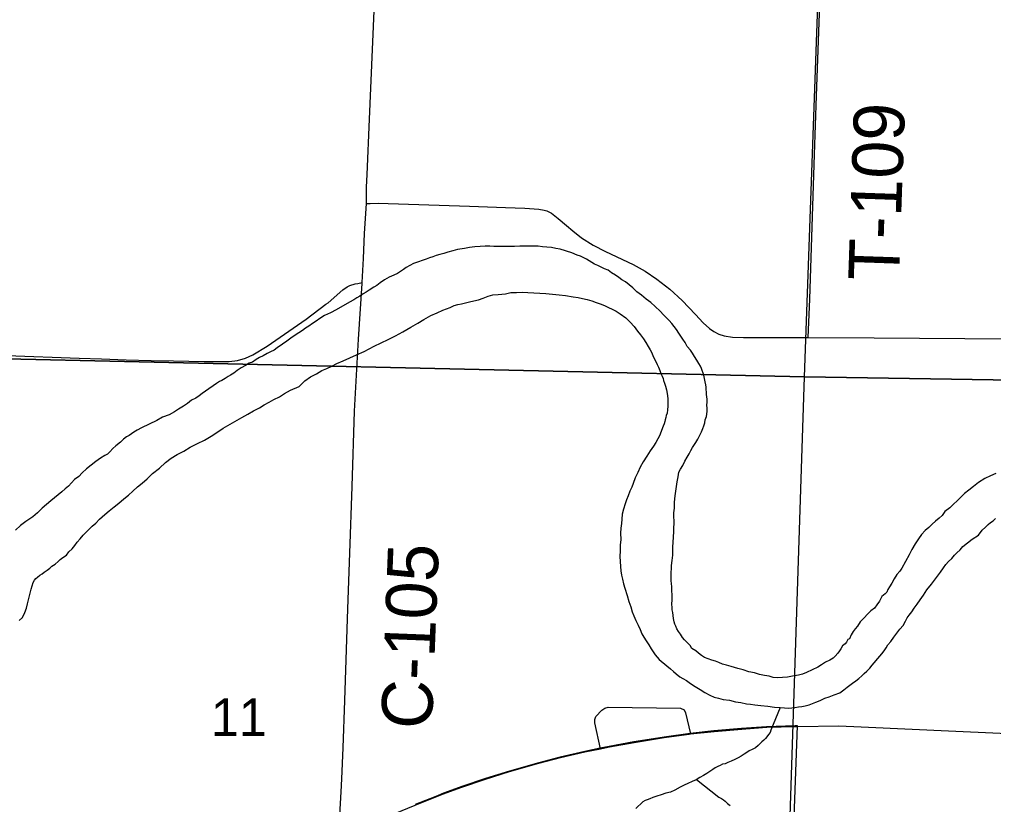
# Model space of a CAD drawing. Extents: x 2.4 to 73.1, y 4.5 to 25.6.
# Drawn here: x 29.555 to 30.099, y 20.902 to 21.341 of the extents above; entities that cross this region are included whole.
import ezdxf

# ---------------------------------------------------------------- set-up
doc = ezdxf.new("R2010")
doc.units = 0
for name, color, linetype in [('GM_X_Corporation', 7, 'Continuous'), ('GM_X_County_Road', 7, 'Continuous'), ('GM_X_County_Road_Text', 7, 'Continuous'), ('GM_X_Interchange_Ramps', 7, 'Continuous'), ('GM_X_Major_River', 7, 'Continuous'), ('GM_X_Minor_River', 7, 'Continuous'), ('GM_X_Section', 7, 'Continuous'), ('GM_X_Section_Text', 7, 'Continuous'), ('GM_X_Township_Road', 7, 'Continuous'), ('GM_X_Township_Road_Text', 7, 'Continuous'), ('GM_X_US_Shield', 7, 'Continuous')]:
    doc.layers.add(name, color=color, linetype=linetype)

msp = doc.modelspace()

# ---------------------------------------------------------------- linework, layer by layer
at = {"layer": 'GM_X_Corporation'}
msp.add_lwpolyline([(29.9783, 20.63829), (29.98962, 20.94583), (29.98829, 20.94583), (29.97224, 20.94531), (29.95828, 20.94435), (29.94277, 20.94304), (29.92959, 20.94158), (29.91498, 20.93958), (29.89808, 20.93689), (29.88431, 20.9344), (29.87929, 20.93336), (29.87059, 20.93156), (29.85696, 20.92837), (29.8449, 20.92525), (29.82845, 20.92053), (29.81508, 20.91636), (29.80182, 20.91189), (29.79158, 20.90816), (29.78727, 20.90644), (29.77572, 20.90185)], dxfattribs=at)
at = {"layer": 'GM_X_County_Road'}
for points in [[(29.74852, 21.23783), (29.74859, 21.24695), (29.74896, 21.25396), (29.75029, 21.28495), (29.75378, 21.36727), (29.75425, 21.38437), (29.75423, 21.3862)], [(29.74616, 21.19359), (29.74686, 21.207), (29.74742, 21.22097), (29.74852, 21.23783)], [(29.73275, 20.88211), (29.73361, 20.89602), (29.73437, 20.90895), (29.73479, 20.9163), (29.73556, 20.93365), (29.73646, 20.96006), (29.73816, 21.01134), (29.73923, 21.04241), (29.74049, 21.07969), (29.74186, 21.12165), (29.74411, 21.162), (29.74613, 21.19303), (29.74616, 21.19359)], [(29.92971, 20.94131), (29.94289, 20.94276), (29.95839, 20.94407), (29.97236, 20.94503), (29.98841, 20.94555), (29.98929, 20.94555)], [(29.98929, 20.94555), (29.98973, 20.94555), (30.01271, 20.94578), (30.02518, 20.94536), (30.0781, 20.9429), (30.11546, 20.94119), (30.18551, 20.93827), (30.21656, 20.93706)], [(29.87941, 20.93308), (29.88442, 20.93412), (29.8982, 20.93662), (29.9151, 20.93931), (29.92897, 20.94123), (29.92971, 20.94131)], [(29.73275, 20.88211), (29.74306, 20.88722), (29.75435, 20.89247), (29.76434, 20.89681), (29.77584, 20.90157), (29.78739, 20.90617), (29.7917, 20.90788), (29.80193, 20.91161), (29.8152, 20.91609), (29.82857, 20.92026), (29.84502, 20.92497), (29.85708, 20.92809), (29.87071, 20.93128), (29.87941, 20.93308)]]:
    msp.add_lwpolyline(points, dxfattribs=at)
at = {"layer": 'GM_X_Interchange_Ramps'}
msp.add_lwpolyline([(29.87941, 20.93308), (29.87631, 20.94754), (29.87631, 20.94934), (29.8768, 20.95107), (29.88025, 20.95469), (29.88189, 20.95576), (29.88378, 20.95622), (29.92415, 20.95576), (29.9262, 20.95477), (29.92702, 20.95304), (29.92971, 20.94131)], dxfattribs=at)
at = {"layer": 'GM_X_Major_River'}
for points in [[(29.84457, 21.21388), (29.84172, 21.21395), (29.83887, 21.21401), (29.8343, 21.21392), (29.83126, 21.2138), (29.82802, 21.21369), (29.82517, 21.21375), (29.82251, 21.21381), (29.81985, 21.21387), (29.81757, 21.21392), (29.81491, 21.21398), (29.81206, 21.21385), (29.8092, 21.21354), (29.80615, 21.21323), (29.80329, 21.21272), (29.79947, 21.21205), (29.79679, 21.21135), (29.79412, 21.21065), (29.79182, 21.20994), (29.78952, 21.20923), (29.78761, 21.2087), (29.78569, 21.20799), (29.78378, 21.20746), (29.78186, 21.20674), (29.77975, 21.20603), (29.77764, 21.20513), (29.77477, 21.20424), (29.77285, 21.20315), (29.77073, 21.20205), (29.76918, 21.20095), (29.76764, 21.19984), (29.7659, 21.19874), (29.76379, 21.19784), (29.76129, 21.19657), (29.7586, 21.19511), (29.75628, 21.19345), (29.75434, 21.19197), (29.75261, 21.19106), (29.7501, 21.18941), (29.74837, 21.18831), (29.74664, 21.1874), (29.7449, 21.18611), (29.74316, 21.18501), (29.74142, 21.18391), (29.73911, 21.18263), (29.73161, 21.17843), (29.72853, 21.17679), (29.72507, 21.17515), (29.72256, 21.1735), (29.72044, 21.17203), (29.71832, 21.17075), (29.71638, 21.16927), (29.71446, 21.16817), (29.71272, 21.16688), (29.71079, 21.1656), (29.70866, 21.16413), (29.70634, 21.16247), (29.70403, 21.16081), (29.70152, 21.15916), (29.69862, 21.15713), (29.69688, 21.15584), (29.69496, 21.15493), (29.69304, 21.15403), (29.69073, 21.15275), (29.6888, 21.15165), (29.68688, 21.15056), (29.68475, 21.14908), (29.68303, 21.14855), (29.68091, 21.14727), (29.67841, 21.146), (29.67628, 21.14453), (29.67435, 21.14305), (29.67261, 21.14195), (29.67126, 21.14103), (29.66953, 21.13993), (29.66856, 21.13938), (29.6676, 21.13883), (29.66645, 21.13829), (29.66471, 21.13719), (29.66278, 21.1359), (29.66046, 21.13424), (29.65853, 21.13296), (29.6566, 21.13167), (29.65505, 21.13038), (29.65312, 21.12909), (29.65081, 21.12781), (29.64849, 21.12596), (29.64618, 21.1245), (29.64348, 21.12285), (29.64116, 21.12138), (29.63828, 21.11973), (29.63444, 21.1183), (29.63136, 21.11647), (29.62271, 21.11249), (29.6204, 21.11121), (29.61847, 21.10992), (29.61712, 21.109), (29.61596, 21.10808), (29.61442, 21.10735), (29.61268, 21.10606), (29.61094, 21.10439)], [(29.91983, 21.04351), (29.91985, 21.04465), (29.91988, 21.04597), (29.92012, 21.04825), (29.9202, 21.05148), (29.92045, 21.05432), (29.92051, 21.05679), (29.92055, 21.05869), (29.92059, 21.06059), (29.92044, 21.06249), (29.9205, 21.06496), (29.92075, 21.06761), (29.92081, 21.07046), (29.92106, 21.07292), (29.92131, 21.07577), (29.92175, 21.07842), (29.92222, 21.0822), (29.92285, 21.08504), (29.92329, 21.08769), (29.92409, 21.08938), (29.92547, 21.09144), (29.92666, 21.09388), (29.92785, 21.09595), (29.92903, 21.09782), (29.93002, 21.0997), (29.93082, 21.10139), (29.93161, 21.10251), (29.93279, 21.10419), (29.93378, 21.10607), (29.93457, 21.10757), (29.93517, 21.1087), (29.93596, 21.1102), (29.93658, 21.11209), (29.93718, 21.11359), (29.93779, 21.11529), (29.93802, 21.11699), (29.93862, 21.11869), (29.93884, 21.12001), (29.93907, 21.12172), (29.93911, 21.12343), (29.93896, 21.12514), (29.939, 21.12685), (29.93903, 21.12837), (29.93887, 21.1297), (29.93871, 21.13104), (29.93843, 21.13522), (29.93827, 21.13655), (29.93792, 21.13808), (29.93758, 21.13999), (29.93725, 21.1419), (29.93689, 21.14304), (29.93635, 21.14438), (29.93581, 21.14554), (29.93526, 21.14688), (29.93435, 21.14842), (29.93325, 21.15034), (29.93196, 21.15227), (29.93087, 21.1542), (29.92977, 21.15593), (29.92791, 21.15787), (29.92682, 21.16018), (29.92553, 21.16191), (29.92442, 21.16365), (29.92313, 21.16539), (29.92185, 21.16732), (29.92055, 21.16906), (29.91926, 21.17079), (29.91778, 21.17235), (29.91629, 21.1739), (29.91462, 21.17565), (29.91276, 21.17759), (29.90997, 21.18031), (29.90755, 21.18246), (29.90493, 21.18441), (29.90232, 21.18656), (29.8997, 21.18852), (29.89747, 21.19066), (29.89541, 21.19242), (29.89336, 21.19398), (29.89129, 21.19517), (29.88961, 21.19654), (29.88774, 21.19772), (29.88549, 21.1991), (29.88362, 21.20047), (29.88174, 21.20127), (29.87986, 21.20226), (29.87797, 21.20307), (29.87609, 21.20387), (29.87459, 21.20485), (29.87309, 21.20583), (29.87159, 21.20663), (29.87009, 21.20742), (29.86821, 21.20841), (29.86632, 21.20903), (29.86331, 21.21023), (29.85689, 21.21228), (29.85443, 21.21271), (29.85196, 21.21315), (29.8495, 21.21339), (29.84703, 21.21364), (29.84457, 21.21388)], [(29.69414, 21.12684), (29.69683, 21.1283), (29.69991, 21.12975), (29.7028, 21.13158), (29.70607, 21.13341), (29.71087, 21.13558), (29.71417, 21.13874), (29.71727, 21.14095), (29.72054, 21.14258), (29.72362, 21.14441), (29.72631, 21.14568), (29.72919, 21.14695), (29.73207, 21.1484), (29.73553, 21.14984), (29.73918, 21.15147), (29.74302, 21.15329), (29.74724, 21.15509), (29.75282, 21.158), (29.75686, 21.16), (29.7607, 21.16182), (29.76474, 21.16382), (29.76897, 21.166), (29.7734, 21.16875), (29.77725, 21.17094), (29.78072, 21.17296), (29.78457, 21.17515), (29.78803, 21.17678), (29.7913, 21.17823), (29.79532, 21.17966), (29.79763, 21.18074), (29.79973, 21.18127), (29.80164, 21.18179), (29.80394, 21.18231), (29.80623, 21.18283), (29.80852, 21.18335), (29.8112, 21.18405), (29.81388, 21.18494), (29.81657, 21.18602), (29.81924, 21.18672), (29.82229, 21.18703), (29.82629, 21.18732), (29.82935, 21.18801), (29.83239, 21.18813), (29.83563, 21.18825), (29.83885, 21.18799), (29.84892, 21.18757), (29.85252, 21.18711), (29.85632, 21.18684), (29.85992, 21.18637), (29.86409, 21.18571), (29.86693, 21.18527), (29.86939, 21.18464), (29.87204, 21.1842), (29.87449, 21.18339), (29.87694, 21.18257), (29.87921, 21.18176), (29.88166, 21.18076), (29.88391, 21.17976), (29.88598, 21.17876), (29.88824, 21.17757), (29.89049, 21.17619), (29.89367, 21.17384), (29.89609, 21.1715), (29.89831, 21.16899), (29.90016, 21.16647), (29.90182, 21.16435), (29.90348, 21.16222), (29.90476, 21.1601), (29.90605, 21.15798), (29.90715, 21.15606), (29.90806, 21.15433), (29.90896, 21.15222), (29.91006, 21.15029), (29.91114, 21.1478), (29.91187, 21.14626), (29.91259, 21.14454), (29.91312, 21.14282), (29.91385, 21.14128), (29.91439, 21.13994), (29.91474, 21.13879), (29.91528, 21.13745), (29.91581, 21.13573), (29.91634, 21.13363), (29.91667, 21.13153), (29.91699, 21.12886), (29.91713, 21.12658), (29.91708, 21.12449), (29.91685, 21.12241), (29.91662, 21.1207), (29.91621, 21.11938), (29.91599, 21.11825), (29.91558, 21.11693), (29.91537, 21.11598), (29.91496, 21.11466), (29.91455, 21.11334), (29.91234, 21.10788), (29.91154, 21.10619), (29.91036, 21.10432), (29.90898, 21.10226), (29.90721, 21.09964), (29.90524, 21.09664)], [(29.55433, 21.00479), (29.55627, 21.00646), (29.55747, 21.00928), (29.55847, 21.01154), (29.5591, 21.01399), (29.55953, 21.01626), (29.561, 21.02231), (29.56161, 21.02419), (29.56222, 21.02589), (29.56301, 21.0272), (29.5636, 21.02814), (29.56457, 21.02888), (29.56592, 21.02999), (29.56727, 21.0309), (29.56843, 21.03183), (29.56998, 21.03293), (29.57152, 21.03404), (29.57269, 21.03515), (29.57443, 21.03625), (29.57617, 21.03773), (29.57734, 21.03885), (29.57869, 21.03996), (29.58081, 21.04124), (29.58218, 21.04311), (29.58393, 21.04478), (29.5855, 21.04664), (29.58687, 21.04851), (29.58843, 21.05038), (29.59019, 21.05243), (29.59175, 21.0541), (29.5933, 21.05559), (29.59524, 21.05744), (29.59718, 21.05911), (29.59932, 21.06134), (29.60223, 21.06393), (29.60475, 21.06597), (29.60746, 21.06819), (29.61017, 21.0704), (29.61289, 21.07281), (29.61541, 21.07485), (29.61793, 21.07707), (29.62045, 21.07948), (29.62316, 21.08151), (29.62587, 21.08392), (29.62898, 21.08689), (29.63285, 21.08984), (29.63616, 21.093), (29.63944, 21.09539), (29.64272, 21.0976), (29.64637, 21.09942), (29.65004, 21.10161), (29.65407, 21.10361), (29.65792, 21.10562), (29.66177, 21.10781), (29.66544, 21.1102), (29.66852, 21.11222), (29.67893, 21.11825), (29.6822, 21.12008), (29.68547, 21.1219), (29.68874, 21.12354), (29.69144, 21.12519), (29.69414, 21.12684)], [(29.61094, 21.10439), (29.60842, 21.10236), (29.60667, 21.10088), (29.60511, 21.09901), (29.60375, 21.09771), (29.60221, 21.09699), (29.5999, 21.09552), (29.5972, 21.09368), (29.59468, 21.09165), (29.59197, 21.08943), (29.58964, 21.0872), (29.58769, 21.08516), (29.58537, 21.0835), (29.58362, 21.08164), (29.58187, 21.07978), (29.58012, 21.0783), (29.57818, 21.07663), (29.57625, 21.07496), (29.57412, 21.0733), (29.57199, 21.07164), (29.56966, 21.0696), (29.56714, 21.06757), (29.56462, 21.06497), (29.56209, 21.06275), (29.55804, 21.05999), (29.55514, 21.05777), (29.55223, 21.05518)], [(29.90524, 21.09664), (29.90327, 21.09346), (29.90168, 21.09045), (29.90028, 21.08745), (29.89888, 21.08444), (29.89767, 21.08124), (29.89687, 21.07935), (29.89587, 21.0771), (29.89486, 21.07446), (29.89405, 21.0722), (29.89324, 21.06994), (29.89222, 21.06692), (29.89158, 21.06409), (29.89133, 21.06143), (29.89109, 21.05897), (29.89084, 21.05631), (29.89058, 21.05347), (29.8907, 21.05005), (29.89044, 21.04683), (29.89036, 21.0436), (29.89029, 21.04056), (29.89042, 21.03771), (29.89055, 21.03486), (29.89087, 21.03257), (29.8912, 21.03009), (29.89172, 21.0278), (29.89223, 21.02532), (29.89294, 21.02283), (29.89436, 21.01862), (29.89524, 21.01537), (29.89631, 21.01231), (29.8972, 21.00963), (29.8981, 21.00733), (29.89918, 21.00465), (29.90046, 21.00215), (29.90154, 20.99966), (29.90244, 20.99736), (29.90373, 20.99543), (29.90501, 20.99331), (29.90649, 20.99119), (29.90776, 20.98888), (29.90887, 20.98714), (29.90997, 20.9856), (29.91108, 20.98424), (29.91219, 20.98289), (29.91649, 20.97937), (29.91854, 20.97781), (29.92022, 20.97625), (29.92171, 20.97489), (29.92376, 20.97332), (29.92545, 20.97233), (29.92752, 20.97115), (29.92976, 20.96958), (29.93239, 20.96781), (29.9352, 20.96623), (29.93782, 20.96446), (29.94064, 20.96306), (29.9429, 20.96187), (29.94536, 20.96125), (29.948, 20.96062), (29.9516, 20.96016), (29.95482, 20.95933), (29.95785, 20.95888), (29.96107, 20.95824), (29.96334, 20.95799), (29.9658, 20.95756), (29.96903, 20.9573), (29.97301, 20.95683), (29.9768, 20.95636), (29.97984, 20.9561), (29.98231, 20.95586), (29.98478, 20.9558), (29.98801, 20.95611), (29.99011, 20.95644), (29.99202, 20.95659), (29.99393, 20.95712), (29.99603, 20.95764), (29.99795, 20.95836), (29.99987, 20.95907), (30.00217, 20.95997), (30.00486, 20.96124), (30.00735, 20.96213), (30.01004, 20.96321), (30.01329, 20.96428), (30.01542, 20.96594), (30.01735, 20.96742), (30.0189, 20.96852), (30.02026, 20.96963), (30.02219, 20.97092), (30.02393, 20.9724), (30.02548, 20.97388), (30.02684, 20.97518), (30.02839, 20.97648), (30.02995, 20.97815), (30.03132, 20.97983), (30.03562, 20.98486), (30.03679, 20.98617), (30.03796, 20.98785), (30.03914, 20.98954), (30.04013, 20.99122), (30.04169, 20.99309)], [(30.10046, 21.08694), (30.09758, 21.08567), (30.09431, 21.08404), (30.09083, 21.08183), (30.08793, 21.07962), (30.08542, 21.07759), (30.0829, 21.07574), (30.08076, 21.07351), (30.07882, 21.07166), (30.07688, 21.0698), (30.07474, 21.06776), (30.07203, 21.06573), (30.07046, 21.06349), (30.06872, 21.06201)], [(30.06872, 21.06201), (30.06678, 21.06034), (30.06484, 21.05867), (30.06309, 21.05681), (30.06096, 21.05496), (30.059, 21.05273), (30.05724, 21.0503), (30.05528, 21.04768), (30.0535, 21.04449), (30.0521, 21.04148), (30.04794, 21.03398), (30.04676, 21.0323), (30.0452, 21.03043), (30.04362, 21.028), (30.04223, 21.02556), (30.04105, 21.02349), (30.04006, 21.022), (30.03946, 21.02049), (30.03868, 21.01956), (30.03674, 21.01808), (30.03535, 21.01545), (30.03398, 21.0134), (30.03261, 21.01172), (30.03067, 21.01005), (30.02873, 21.0082), (30.02678, 21.00615), (30.02464, 21.00392), (30.02306, 21.00148), (30.02189, 20.99999), (30.02071, 20.9985), (30.01954, 20.99681), (30.01873, 20.99455), (30.01777, 20.99419), (30.01697, 20.99269), (30.01619, 20.99176), (30.01483, 20.99065), (30.01385, 20.98896), (30.01306, 20.98784), (30.01208, 20.98653), (30.01071, 20.98485), (30.00955, 20.98374), (30.00762, 20.98265), (30.00531, 20.98137), (30.003, 20.9799), (30.00088, 20.97862), (29.99454, 20.97572), (29.99243, 20.97482), (29.99013, 20.97411), (29.9867, 20.97362), (29.98402, 20.97311), (29.98117, 20.97279), (29.9785, 20.97266), (29.97603, 20.97291), (29.97377, 20.97353), (29.97112, 20.97397), (29.96828, 20.9746), (29.96544, 20.97542), (29.96242, 20.97606), (29.95921, 20.97708), (29.95619, 20.97791), (29.95241, 20.97895), (29.94995, 20.97976), (29.94769, 20.98038), (29.94561, 20.98119), (29.94373, 20.98199), (29.94165, 20.98261), (29.93958, 20.98322), (29.9375, 20.98403), (29.93582, 20.98521), (29.93413, 20.98639), (29.93264, 20.98775), (29.93058, 20.98913), (29.92948, 20.99067), (29.92836, 20.99183), (29.92743, 20.99281), (29.92632, 20.99397), (29.92521, 20.99532), (29.92411, 20.99706), (29.923, 20.9986), (29.92208, 21.00014), (29.92155, 21.00149), (29.921, 21.00264), (29.92065, 21.00397), (29.92031, 21.00588), (29.91997, 21.0076), (29.91982, 21.00912), (29.91947, 21.01065), (29.9195, 21.01198), (29.91935, 21.01388), (29.91941, 21.01635), (29.91947, 21.01901), (29.91933, 21.02129), (29.91938, 21.02357), (29.91904, 21.02548), (29.91889, 21.027), (29.919, 21.03194), (29.91903, 21.03346), (29.91908, 21.03554), (29.91952, 21.03819), (29.91978, 21.04123), (29.91983, 21.04351)], [(30.04169, 20.99309), (30.04346, 20.99533), (30.04503, 20.99757), (30.04679, 20.99981), (30.04874, 21.00186), (30.04993, 21.0043), (30.05092, 21.00618), (30.0521, 21.00767), (30.05347, 21.00954), (30.05485, 21.0116), (30.05642, 21.01384), (30.05818, 21.01627), (30.05995, 21.01889), (30.06192, 21.02189), (30.06447, 21.02506), (30.06681, 21.02804), (30.06956, 21.03178), (30.07114, 21.03422), (30.07251, 21.03609), (30.07407, 21.03776), (30.07581, 21.03943), (30.07738, 21.04129), (30.07874, 21.04259), (30.08049, 21.04426), (30.08205, 21.04613), (30.08457, 21.04816), (30.08727, 21.05019), (30.09074, 21.05239), (30.0929, 21.05519), (30.09465, 21.05686), (30.0962, 21.05835), (30.09756, 21.05946), (30.09891, 21.06038), (30.10027, 21.06168)]]:
    msp.add_lwpolyline(points, dxfattribs=at)
at = {"layer": 'GM_X_Minor_River'}
for points in [[(29.97994, 20.95609), (29.97461, 20.94349), (29.9742, 20.94217), (29.97342, 20.94105), (29.97244, 20.93974), (29.97166, 20.93881), (29.97069, 20.93788), (29.96971, 20.93696), (29.96874, 20.93603), (29.96758, 20.93491), (29.96603, 20.93362), (29.9643, 20.93271), (29.96256, 20.9318), (29.96121, 20.93088), (29.95967, 20.92996), (29.95813, 20.92886), (29.95639, 20.92795), (29.95447, 20.92704), (29.95255, 20.92613), (29.95063, 20.92542), (29.9491, 20.92469), (29.94757, 20.92435), (29.94641, 20.92361), (29.94507, 20.92307), (29.94353, 20.92235), (29.94218, 20.92143), (29.94063, 20.92032), (29.9389, 20.91922), (29.93697, 20.91813), (29.93505, 20.91703), (29.93293, 20.91575), (29.93062, 20.91466), (29.92832, 20.91357), (29.9262, 20.91267), (29.9239, 20.91158), (29.92101, 20.90994), (29.91851, 20.90885), (29.91603, 20.90815), (29.91335, 20.90726), (29.91086, 20.90655), (29.90875, 20.90584), (29.90702, 20.90512), (29.90549, 20.90458), (29.90434, 20.90404), (29.90318, 20.90331), (29.89911, 20.8996)], [(29.93301, 20.9158), (29.94564, 20.90596), (29.94714, 20.90517), (29.94826, 20.90457), (29.9492, 20.90379), (29.9505, 20.90243), (29.95199, 20.90126)]]:
    msp.add_lwpolyline(points, dxfattribs=at)
at = {"layer": 'GM_X_Section'}
for points in [[(30.51643, 21.65196), (30.49787, 21.13293), (29.99357, 21.14088), (30.01225, 21.66591), (30.01568, 21.66582)], [(30.48067, 20.63017), (29.97714, 20.63847), (29.99357, 21.14088), (30.49787, 21.13293)]]:
    msp.add_lwpolyline(points, close=True, dxfattribs=at)
at = {"layer": 'GM_X_Township_Road'}
for points in [[(29.99549, 21.16297), (29.99647, 21.1844), (29.9991, 21.26527), (30.00015, 21.29793), (30.00202, 21.34924), (30.00343, 21.39082)], [(29.74616, 21.19359), (29.74686, 21.207), (29.74742, 21.22097), (29.74852, 21.23783)], [(29.74852, 21.23783), (29.7506, 21.23787), (29.75508, 21.23796), (29.80617, 21.23626), (29.82631, 21.23567), (29.83714, 21.23524), (29.84486, 21.23469), (29.84791, 21.23418), (29.84932, 21.23373), (29.85203, 21.23234), (29.85573, 21.22952), (29.86042, 21.22547), (29.86401, 21.22254), (29.86887, 21.21871), (29.8754, 21.21455), (29.88225, 21.21093), (29.89765, 21.20367), (29.90442, 21.19992), (29.91086, 21.19561), (29.91819, 21.18989), (29.92507, 21.18363), (29.93248, 21.17571), (29.93681, 21.17108), (29.94032, 21.16795), (29.94286, 21.16619), (29.94559, 21.1648), (29.94855, 21.1639), (29.95314, 21.16317), (29.95932, 21.16288), (29.99549, 21.16297)], [(29.49738, 21.15402), (29.54755, 21.15277), (29.58793, 21.15135), (29.60033, 21.15093), (29.61427, 21.15036), (29.62825, 21.15004), (29.64067, 21.14989), (29.65774, 21.14958), (29.67173, 21.14955), (29.67636, 21.15005), (29.68084, 21.15128), (29.68507, 21.15323), (29.693, 21.15814), (29.71476, 21.17312), (29.72593, 21.18147), (29.72718, 21.18225), (29.73532, 21.18947), (29.73784, 21.19126), (29.73922, 21.19196), (29.7422, 21.19284), (29.74372, 21.19313), (29.74616, 21.19359)], [(29.99549, 21.16297), (30.03239, 21.16265), (30.10852, 21.16211)]]:
    msp.add_lwpolyline(points, dxfattribs=at)
at = {"layer": 'GM_X_US_Shield'}
for points in [[(29.49738, 21.3687), (29.49738, 21.15205), (29.99357, 21.14088), (30.01225, 21.66591), (29.50805, 21.67827)], [(29.49738, 21.15205), (29.49738, 20.65341), (29.97714, 20.63847), (29.99357, 21.14088)]]:
    msp.add_lwpolyline(points, close=True, dxfattribs=at)

# ---------------------------------------------------------------- texts
at = {"layer": 'GM_X_County_Road_Text'}
msp.add_text('C-105', height=0.028409, rotation=87.7973, dxfattribs=at).set_placement((29.78509, 20.94372))
at = {"layer": 'GM_X_Section_Text'}
msp.add_text('11', height=0.020928, rotation=0, dxfattribs=at).set_placement((29.6616, 20.94023))
at = {"layer": 'GM_X_Township_Road_Text'}
msp.add_text('T-109', height=0.028409, rotation=88.0348, dxfattribs=at).set_placement((30.0463, 21.19434))

doc.saveas('drawing.dxf')
